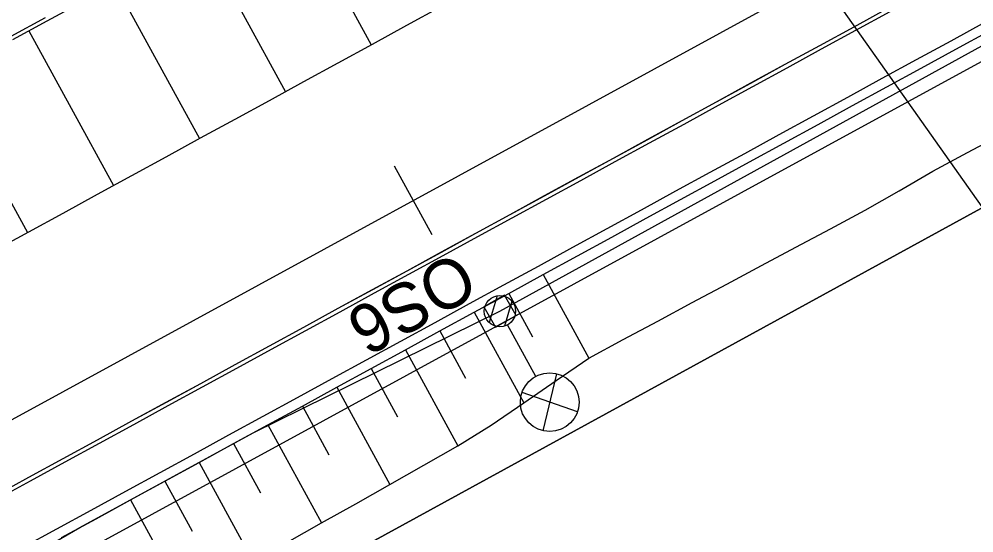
# Model space of a CAD drawing. Extents: x -783978 to -783565, y -1064821 to -1064596.
# Drawn here: x -783852.22 to -783827.85, y -1064732.75 to -1064719.63 of the extents above; entities that cross this region are included whole.
import ezdxf

# ---------------------------------------------------------------- set-up
doc = ezdxf.new("R2010")
doc.units = 0
for name, color, linetype in [('_PS_SO_číslo', 7, 'Continuous'), ('PS 01_01_10', 7, 'Continuous'), ('PS 01_02_501', 7, 'Continuous'), ('PS 01_02_502', 7, 'Continuous'), ('SO 01_50_01', 7, 'Continuous'), ('SO 01_79_02', 7, 'Continuous'), ('SO 01_86_02', 7, 'Continuous'), ('SO 01_86_03', 7, 'Continuous')]:
    doc.layers.add(name, color=color, linetype=linetype)

msp = doc.modelspace()

# ---------------------------------------------------------------- linework, layer by layer
at = {"layer": '_PS_SO_číslo'}
msp.add_line((-783827.638, -1064724.425), (-783849.035, -1064694.16), dxfattribs=at)
at = {"layer": 'PS 01_01_10'}
msp.add_lwpolyline([(-783718.942, -1064658.936), (-783725.964, -1064662.689), (-783732.354, -1064665.912), (-783735.21, -1064660.697), (-783789.362, -1064690.348), (-783783.825, -1064700.441), (-783871.436, -1064748.425), (-783875.857, -1064749.835)], dxfattribs=at)
at = {"layer": 'PS 01_02_501'}
msp.add_lwpolyline([(-783952.311, -1064789.972), (-783925.027, -1064771.233), (-783922.857, -1064767.935), (-783921.132, -1064767.225), (-783922.344, -1064769.056), (-783920.816, -1064771.043), (-783917.67, -1064770.417), (-783911.05, -1064766.471), (-783887.429, -1064753.525), (-783871.436, -1064748.425), (-783783.828, -1064700.439), (-783789.362, -1064690.348), (-783735.226, -1064660.707), (-783727.19, -1064659.072), (-783724.297, -1064658.484), (-783715.521, -1064653.988), (-783697.391, -1064644.148), (-783676.268, -1064633.506), (-783655.138, -1064621.894)], dxfattribs=at)
at = {"layer": 'PS 01_02_502'}
msp.add_lwpolyline([(-783952.311, -1064789.972), (-783925.027, -1064771.233), (-783922.857, -1064767.935), (-783921.132, -1064767.225), (-783922.344, -1064769.056), (-783920.816, -1064771.043), (-783917.67, -1064770.417), (-783911.05, -1064766.471), (-783887.429, -1064753.525), (-783871.436, -1064748.425), (-783783.828, -1064700.439), (-783789.362, -1064690.348), (-783735.226, -1064660.707), (-783727.19, -1064659.072), (-783724.297, -1064658.484), (-783715.521, -1064653.988), (-783697.391, -1064644.148), (-783676.268, -1064633.506), (-783655.138, -1064621.894)], dxfattribs=at)
at = {"layer": 'SO 01_50_01'}
for p, q in [((-783867.163, -1064737.91), (-783786.213, -1064693.707)), ((-783851.5, -1064719.673), (-783850.622, -1064719.193)), ((-783842.322, -1064719.788), (-783841.444, -1064719.309)), ((-783830.909, -1064719.823), (-783830.032, -1064719.343)), ((-783830.909, -1064719.824), (-783830.031, -1064719.344)), ((-783830.861, -1064719.91), (-783829.984, -1064719.431)), ((-783852.426, -1064720.064), (-783851.548, -1064719.585)), ((-783852.426, -1064720.064), (-783851.548, -1064719.585)), ((-783852.426, -1064720.064), (-783851.548, -1064719.585)), ((-783852.378, -1064720.152), (-783851.5, -1064719.673)), ((-783828.435, -1064720.181), (-783827.557, -1064719.701)), ((-783843.2, -1064720.267), (-783842.322, -1064719.788)), ((-783831.787, -1064720.302), (-783830.909, -1064719.823)), ((-783831.787, -1064720.303), (-783830.909, -1064719.824)), ((-783831.739, -1064720.39), (-783830.861, -1064719.91)), ((-783828.315, -1064720.4), (-783827.438, -1064719.921)), ((-783828.315, -1064720.4), (-783827.438, -1064719.921)), ((-783828.315, -1064720.4), (-783827.438, -1064719.921)), ((-783829.313, -1064720.66), (-783828.435, -1064720.181)), ((-783844.077, -1064720.747), (-783843.2, -1064720.267)), ((-783832.665, -1064720.781), (-783831.787, -1064720.302)), ((-783832.664, -1064720.782), (-783831.787, -1064720.303)), ((-783832.617, -1064720.869), (-783831.739, -1064720.39)), ((-783829.193, -1064720.879), (-783828.315, -1064720.4)), ((-783829.193, -1064720.879), (-783828.315, -1064720.4)), ((-783829.193, -1064720.879), (-783828.315, -1064720.4)), ((-783830.19, -1064721.139), (-783829.313, -1064720.66)), ((-783844.955, -1064721.226), (-783844.077, -1064720.747)), ((-783833.542, -1064721.26), (-783832.665, -1064720.781)), ((-783833.542, -1064721.261), (-783832.664, -1064720.782)), ((-783833.494, -1064721.348), (-783832.617, -1064720.869)), ((-783830.071, -1064721.359), (-783829.193, -1064720.879)), ((-783830.071, -1064721.359), (-783829.193, -1064720.879)), ((-783830.071, -1064721.359), (-783829.193, -1064720.879)), ((-783831.068, -1064721.618), (-783830.19, -1064721.139)), ((-783845.833, -1064721.705), (-783844.955, -1064721.226)), ((-783834.42, -1064721.74), (-783833.542, -1064721.26)), ((-783834.42, -1064721.741), (-783833.542, -1064721.261)), ((-783834.372, -1064721.828), (-783833.494, -1064721.348)), ((-783830.948, -1064721.838), (-783830.071, -1064721.359)), ((-783830.948, -1064721.838), (-783830.071, -1064721.359)), ((-783830.948, -1064721.838), (-783830.071, -1064721.359)), ((-783831.946, -1064722.098), (-783831.068, -1064721.618)), ((-783846.71, -1064722.184), (-783845.833, -1064721.705)), ((-783835.298, -1064722.219), (-783834.42, -1064721.74)), ((-783835.297, -1064722.22), (-783834.42, -1064721.741)), ((-783835.25, -1064722.307), (-783834.372, -1064721.828)), ((-783831.826, -1064722.317), (-783830.948, -1064721.838)), ((-783831.826, -1064722.317), (-783830.948, -1064721.838)), ((-783831.826, -1064722.317), (-783830.948, -1064721.838)), ((-783832.823, -1064722.577), (-783831.946, -1064722.098)), ((-783847.588, -1064722.664), (-783846.71, -1064722.184)), ((-783836.175, -1064722.698), (-783835.298, -1064722.219)), ((-783836.175, -1064722.699), (-783835.297, -1064722.22)), ((-783836.127, -1064722.786), (-783835.25, -1064722.307)), ((-783832.704, -1064722.796), (-783831.826, -1064722.317)), ((-783832.704, -1064722.796), (-783831.826, -1064722.317)), ((-783832.704, -1064722.796), (-783831.826, -1064722.317)), ((-783833.701, -1064723.056), (-783832.823, -1064722.577)), ((-783828.015, -1064723.037), (-783827.132, -1064722.567)), ((-783848.466, -1064723.143), (-783847.588, -1064722.664)), ((-783837.053, -1064723.178), (-783836.175, -1064722.698)), ((-783837.053, -1064723.178), (-783836.175, -1064722.699)), ((-783837.005, -1064723.265), (-783836.127, -1064722.786)), ((-783833.581, -1064723.276), (-783832.704, -1064722.796)), ((-783833.581, -1064723.276), (-783832.704, -1064722.796)), ((-783833.581, -1064723.276), (-783832.704, -1064722.796)), ((-783834.579, -1064723.536), (-783833.701, -1064723.056)), ((-783828.897, -1064723.508), (-783828.015, -1064723.037)), ((-783849.343, -1064723.622), (-783848.466, -1064723.143)), ((-783837.931, -1064723.657), (-783837.053, -1064723.178)), ((-783837.93, -1064723.658), (-783837.053, -1064723.178)), ((-783837.883, -1064723.745), (-783837.005, -1064723.265)), ((-783834.459, -1064723.755), (-783833.581, -1064723.276)), ((-783834.459, -1064723.755), (-783833.581, -1064723.276)), ((-783834.459, -1064723.755), (-783833.581, -1064723.276)), ((-783841.681, -1064725.135), (-783842.64, -1064723.38)), ((-783835.456, -1064724.015), (-783834.579, -1064723.536)), ((-783829.76, -1064724.014), (-783828.897, -1064723.508)), ((-783850.221, -1064724.101), (-783849.343, -1064723.622)), ((-783838.808, -1064724.136), (-783837.931, -1064723.657)), ((-783838.808, -1064724.137), (-783837.93, -1064723.658)), ((-783838.76, -1064724.224), (-783837.883, -1064723.745)), ((-783835.337, -1064724.234), (-783834.459, -1064723.755)), ((-783835.337, -1064724.234), (-783834.459, -1064723.755)), ((-783835.337, -1064724.234), (-783834.459, -1064723.755)), ((-783851.099, -1064724.581), (-783850.221, -1064724.101)), ((-783836.334, -1064724.494), (-783835.456, -1064724.015)), ((-783830.63, -1064724.507), (-783829.76, -1064724.014)), ((-783839.686, -1064724.615), (-783838.808, -1064724.136)), ((-783839.686, -1064724.616), (-783838.808, -1064724.137)), ((-783839.638, -1064724.703), (-783838.76, -1064724.224)), ((-783836.214, -1064724.713), (-783835.337, -1064724.234)), ((-783836.214, -1064724.713), (-783835.337, -1064724.234)), ((-783836.214, -1064724.713), (-783835.337, -1064724.234)), ((-783851.976, -1064725.06), (-783851.099, -1064724.581)), ((-783837.212, -1064724.973), (-783836.334, -1064724.494)), ((-783831.512, -1064724.979), (-783830.63, -1064724.507)), ((-783840.564, -1064725.095), (-783839.686, -1064724.615)), ((-783840.563, -1064725.095), (-783839.686, -1064724.616)), ((-783840.516, -1064725.182), (-783839.638, -1064724.703)), ((-783837.092, -1064725.193), (-783836.214, -1064724.713)), ((-783837.092, -1064725.193), (-783836.214, -1064724.713)), ((-783837.092, -1064725.193), (-783836.214, -1064724.713)), ((-783852.854, -1064725.539), (-783851.976, -1064725.06)), ((-783838.09, -1064725.453), (-783837.212, -1064724.973)), ((-783832.394, -1064725.451), (-783831.512, -1064724.979)), ((-783841.441, -1064725.575), (-783840.563, -1064725.095)), ((-783841.441, -1064725.574), (-783840.564, -1064725.095)), ((-783841.393, -1064725.662), (-783840.516, -1064725.182)), ((-783837.97, -1064725.672), (-783837.092, -1064725.193)), ((-783837.97, -1064725.672), (-783837.092, -1064725.193)), ((-783837.97, -1064725.672), (-783837.092, -1064725.193)), ((-783838.967, -1064725.932), (-783838.09, -1064725.453)), ((-783833.275, -1064725.923), (-783832.394, -1064725.451)), ((-783842.319, -1064726.053), (-783841.441, -1064725.574)), ((-783842.319, -1064726.054), (-783841.441, -1064725.575)), ((-783842.271, -1064726.141), (-783841.393, -1064725.662)), ((-783838.847, -1064726.151), (-783837.97, -1064725.672)), ((-783838.847, -1064726.151), (-783837.97, -1064725.672)), ((-783838.847, -1064726.151), (-783837.97, -1064725.672)), ((-783843.197, -1064726.532), (-783842.319, -1064726.053)), ((-783843.196, -1064726.533), (-783842.319, -1064726.054)), ((-783839.845, -1064726.411), (-783838.967, -1064725.932)), ((-783834.157, -1064726.395), (-783833.275, -1064725.923)), ((-783843.149, -1064726.62), (-783842.271, -1064726.141)), ((-783839.725, -1064726.63), (-783838.847, -1064726.151)), ((-783839.725, -1064726.63), (-783838.847, -1064726.151)), ((-783839.725, -1064726.63), (-783838.847, -1064726.151)), ((-783838.847, -1064726.151), (-783837.681, -1064728.288)), ((-783844.074, -1064727.012), (-783843.197, -1064726.532)), ((-783844.074, -1064727.012), (-783843.196, -1064726.533)), ((-783840.723, -1064726.89), (-783839.845, -1064726.411)), ((-783835.039, -1064726.866), (-783834.157, -1064726.395)), ((-783844.027, -1064727.099), (-783843.149, -1064726.62)), ((-783840.603, -1064727.11), (-783839.725, -1064726.63)), ((-783840.603, -1064727.11), (-783839.725, -1064726.63)), ((-783840.603, -1064727.11), (-783839.725, -1064726.63)), ((-783839.725, -1064726.63), (-783839.118, -1064727.743)), ((-783844.952, -1064727.492), (-783844.074, -1064727.012)), ((-783844.952, -1064727.491), (-783844.074, -1064727.012)), ((-783841.6, -1064727.37), (-783840.723, -1064726.89)), ((-783835.92, -1064727.338), (-783835.039, -1064726.866)), ((-783844.904, -1064727.579), (-783844.027, -1064727.099)), ((-783841.48, -1064727.589), (-783840.603, -1064727.11)), ((-783841.48, -1064727.589), (-783840.603, -1064727.11)), ((-783841.48, -1064727.589), (-783840.603, -1064727.11)), ((-783840.603, -1064727.11), (-783839.339, -1064729.424)), ((-783845.83, -1064727.97), (-783844.952, -1064727.491)), ((-783845.829, -1064727.971), (-783844.952, -1064727.492)), ((-783842.478, -1064727.849), (-783841.6, -1064727.37)), ((-783836.802, -1064727.81), (-783835.92, -1064727.338)), ((-783845.782, -1064728.058), (-783844.904, -1064727.579)), ((-783842.358, -1064728.068), (-783841.48, -1064727.589)), ((-783842.358, -1064728.068), (-783841.48, -1064727.589)), ((-783842.358, -1064728.068), (-783841.48, -1064727.589)), ((-783841.48, -1064727.589), (-783840.824, -1064728.791)), ((-783846.707, -1064728.449), (-783845.83, -1064727.97)), ((-783846.707, -1064728.45), (-783845.829, -1064727.971)), ((-783843.356, -1064728.328), (-783842.478, -1064727.849)), ((-783837.681, -1064728.288), (-783836.802, -1064727.81)), ((-783846.66, -1064728.537), (-783845.782, -1064728.058)), ((-783843.236, -1064728.547), (-783842.358, -1064728.068)), ((-783843.236, -1064728.547), (-783842.358, -1064728.068)), ((-783843.236, -1064728.547), (-783842.358, -1064728.068)), ((-783842.358, -1064728.068), (-783841.019, -1064730.521)), ((-783847.585, -1064728.929), (-783846.707, -1064728.449)), ((-783847.585, -1064728.929), (-783846.707, -1064728.45)), ((-783844.233, -1064728.807), (-783843.356, -1064728.328)), ((-783838.51, -1064728.856), (-783837.681, -1064728.288)), ((-783847.537, -1064729.016), (-783846.66, -1064728.537)), ((-783844.113, -1064729.027), (-783843.236, -1064728.547)), ((-783844.113, -1064729.027), (-783843.236, -1064728.547)), ((-783844.113, -1064729.027), (-783843.236, -1064728.547)), ((-783843.236, -1064728.547), (-783842.562, -1064729.78)), ((-783848.463, -1064729.408), (-783847.585, -1064728.929)), ((-783848.462, -1064729.409), (-783847.585, -1064728.929)), ((-783845.111, -1064729.287), (-783844.233, -1064728.807)), ((-783839.339, -1064729.424), (-783838.51, -1064728.856)), ((-783848.415, -1064729.496), (-783847.537, -1064729.016)), ((-783844.991, -1064729.506), (-783844.113, -1064729.027)), ((-783844.991, -1064729.506), (-783844.113, -1064729.027)), ((-783844.991, -1064729.506), (-783844.113, -1064729.027)), ((-783844.113, -1064729.027), (-783842.759, -1064731.507)), ((-783849.34, -1064729.887), (-783848.463, -1064729.408)), ((-783849.34, -1064729.888), (-783848.462, -1064729.409)), ((-783845.989, -1064729.766), (-783845.111, -1064729.287)), ((-783840.168, -1064729.993), (-783839.339, -1064729.424)), ((-783849.293, -1064729.975), (-783848.415, -1064729.496)), ((-783845.869, -1064729.985), (-783844.991, -1064729.506)), ((-783845.869, -1064729.985), (-783844.991, -1064729.506)), ((-783845.869, -1064729.985), (-783844.991, -1064729.506)), ((-783844.991, -1064729.506), (-783844.311, -1064730.753)), ((-783850.218, -1064730.366), (-783849.34, -1064729.887)), ((-783850.218, -1064730.367), (-783849.34, -1064729.888)), ((-783846.866, -1064730.245), (-783845.989, -1064729.766)), ((-783850.17, -1064730.454), (-783849.293, -1064729.975)), ((-783846.746, -1064730.465), (-783845.869, -1064729.985)), ((-783846.746, -1064730.465), (-783845.869, -1064729.985)), ((-783846.746, -1064730.465), (-783845.869, -1064729.985)), ((-783845.869, -1064729.985), (-783844.5, -1064732.492)), ((-783841.019, -1064730.521), (-783840.168, -1064729.993)), ((-783851.096, -1064730.846), (-783850.218, -1064730.366)), ((-783851.095, -1064730.846), (-783850.218, -1064730.367)), ((-783847.744, -1064730.724), (-783846.866, -1064730.245)), ((-783851.048, -1064730.933), (-783850.17, -1064730.454)), ((-783847.624, -1064730.944), (-783846.746, -1064730.465)), ((-783847.624, -1064730.944), (-783846.746, -1064730.465)), ((-783847.624, -1064730.944), (-783846.746, -1064730.465)), ((-783846.746, -1064730.465), (-783846.058, -1064731.725)), ((-783841.889, -1064731.014), (-783841.019, -1064730.521)), ((-783851.974, -1064731.325), (-783851.096, -1064730.846)), ((-783851.973, -1064731.326), (-783851.095, -1064730.846)), ((-783848.622, -1064731.204), (-783847.744, -1064730.724)), ((-783851.926, -1064731.413), (-783851.048, -1064730.933)), ((-783848.502, -1064731.423), (-783847.624, -1064730.944)), ((-783848.502, -1064731.423), (-783847.624, -1064730.944)), ((-783848.502, -1064731.423), (-783847.624, -1064730.944)), ((-783847.624, -1064730.944), (-783846.24, -1064733.478)), ((-783842.759, -1064731.507), (-783841.889, -1064731.014)), ((-783852.851, -1064731.804), (-783851.974, -1064731.325)), ((-783852.851, -1064731.805), (-783851.973, -1064731.326)), ((-783852.803, -1064731.892), (-783851.926, -1064731.413)), ((-783849.499, -1064731.683), (-783848.622, -1064731.204)), ((-783849.379, -1064731.902), (-783848.502, -1064731.423)), ((-783849.379, -1064731.902), (-783848.502, -1064731.423)), ((-783849.379, -1064731.902), (-783848.502, -1064731.423)), ((-783848.502, -1064731.423), (-783847.807, -1064732.697)), ((-783843.63, -1064732), (-783842.759, -1064731.507)), ((-783850.377, -1064732.162), (-783849.499, -1064731.683)), ((-783850.257, -1064732.382), (-783849.379, -1064731.902)), ((-783850.257, -1064732.382), (-783849.379, -1064731.902)), ((-783850.257, -1064732.382), (-783849.379, -1064731.902)), ((-783849.379, -1064731.902), (-783847.981, -1064734.463)), ((-783844.5, -1064732.492), (-783843.63, -1064732)), ((-783851.255, -1064732.641), (-783850.377, -1064732.162)), ((-783851.135, -1064732.861), (-783850.257, -1064732.382)), ((-783851.135, -1064732.861), (-783850.257, -1064732.382)), ((-783851.135, -1064732.861), (-783850.257, -1064732.382)), ((-783845.37, -1064732.985), (-783844.5, -1064732.492)), ((-783852.132, -1064733.121), (-783851.255, -1064732.641))]:
    msp.add_line(p, q, dxfattribs=at)
for points in [[(-783845.388, -1064716.335), (-783843.231, -1064720.284)], [(-783847.582, -1064717.533), (-783845.425, -1064721.483)], [(-783849.776, -1064718.731), (-783847.619, -1064722.681)], [(-783851.97, -1064719.929), (-783849.814, -1064723.879)], [(-783854.165, -1064721.127), (-783852.008, -1064725.077)]]:
    msp.add_lwpolyline(points, dxfattribs=at)
at = {"layer": 'SO 01_79_02'}
msp.add_lwpolyline([(-783745.082, -1064674.977), (-783746.507, -1064675.757), (-783748.147, -1064676.664), (-783749.691, -1064678.136), (-783784.257, -1064697.013), (-783798.19, -1064704.62), (-783800.06, -1064705.37), (-783802.52, -1064706.72), (-783803.71, -1064707.63), (-783853.11, -1064734.61), (-783855.1, -1064735.3), (-783857.05, -1064736.37), (-783858.65, -1064737.64), (-783871.68, -1064744.75), (-783877.056, -1064744.607), (-783887.429, -1064744.062), (-783898.089, -1064743.49), (-783899.421, -1064743.418)], dxfattribs=at)
at = {"layer": 'SO 01_86_02'}
for p, q in [((-783840.021, -1064726.697), (-783840.221, -1064727.375)), ((-783839.644, -1064726.829), (-783839.831, -1064727.465)), ((-783839.036, -1064728.753), (-783839.755, -1064727.437)), ((-783838.505, -1064728.682), (-783838.851, -1064730.138)), ((-783837.971, -1064729.658), (-783839.384, -1064729.162))]:
    msp.add_line(p, q, dxfattribs=at)
msp.add_lwpolyline([(-783878.186, -1064744.275), (-783875.129, -1064744.345), (-783874.695, -1064744.328), (-783873.251, -1064744.157), (-783872.314, -1064743.982), (-783871.219, -1064743.702), (-783870.515, -1064743.486), (-783869.798, -1064743.212), (-783869.177, -1064742.975), (-783868.711, -1064742.765), (-783868.395, -1064742.607), (-783868.078, -1064742.449), (-783860.975, -1064738.569), (-783850.672, -1064732.611), (-783846.246, -1064730.189), (-783839.947, -1064727.086), (-783822.426, -1064717.427), (-783813.356, -1064712.518), (-783804.285, -1064707.61), (-783794.474, -1064702.252), (-783784.661, -1064696.896), (-783775.734, -1064692.013), (-783766.806, -1064687.131), (-783750.626, -1064678.282)], dxfattribs=at)
msp.add_lwpolyline([(-783840.061, -1064727.494), (-783839.538, -1064727.199), (-783839.833, -1064726.677), (-783840.356, -1064726.972)], close=True, dxfattribs=at)
for centre, radius in [((-783839.947, -1064727.086), 0.4), ((-783838.678, -1064729.41), 0.749)]:
    msp.add_circle(centre, radius, dxfattribs=at)
at = {"layer": 'SO 01_86_03'}
msp.add_lwpolyline([(-783722.521, -1064661.793), (-783724.821, -1064663.049), (-783735.21, -1064660.697), (-783787.333, -1064689.237), (-783786.817, -1064690.18), (-783783.359, -1064696.803), (-783781.939, -1064699.409), (-783783.828, -1064700.439), (-783871.436, -1064748.425), (-783875.857, -1064749.835), (-783877.538, -1064747.393), (-783875.857, -1064749.835), (-783887.429, -1064753.525), (-783911.05, -1064766.471), (-783917.67, -1064770.417), (-783920.816, -1064771.043), (-783922.344, -1064769.056), (-783922.498, -1064767.051)], dxfattribs=at)

# ---------------------------------------------------------------- texts
at = {"layer": 'SO 01_86_02'}
msp.add_text('OS6', height=1.25, rotation=209.446, dxfattribs=at).set_placement((-783841.038, -1064725.526))

doc.saveas('drawing.dxf')
